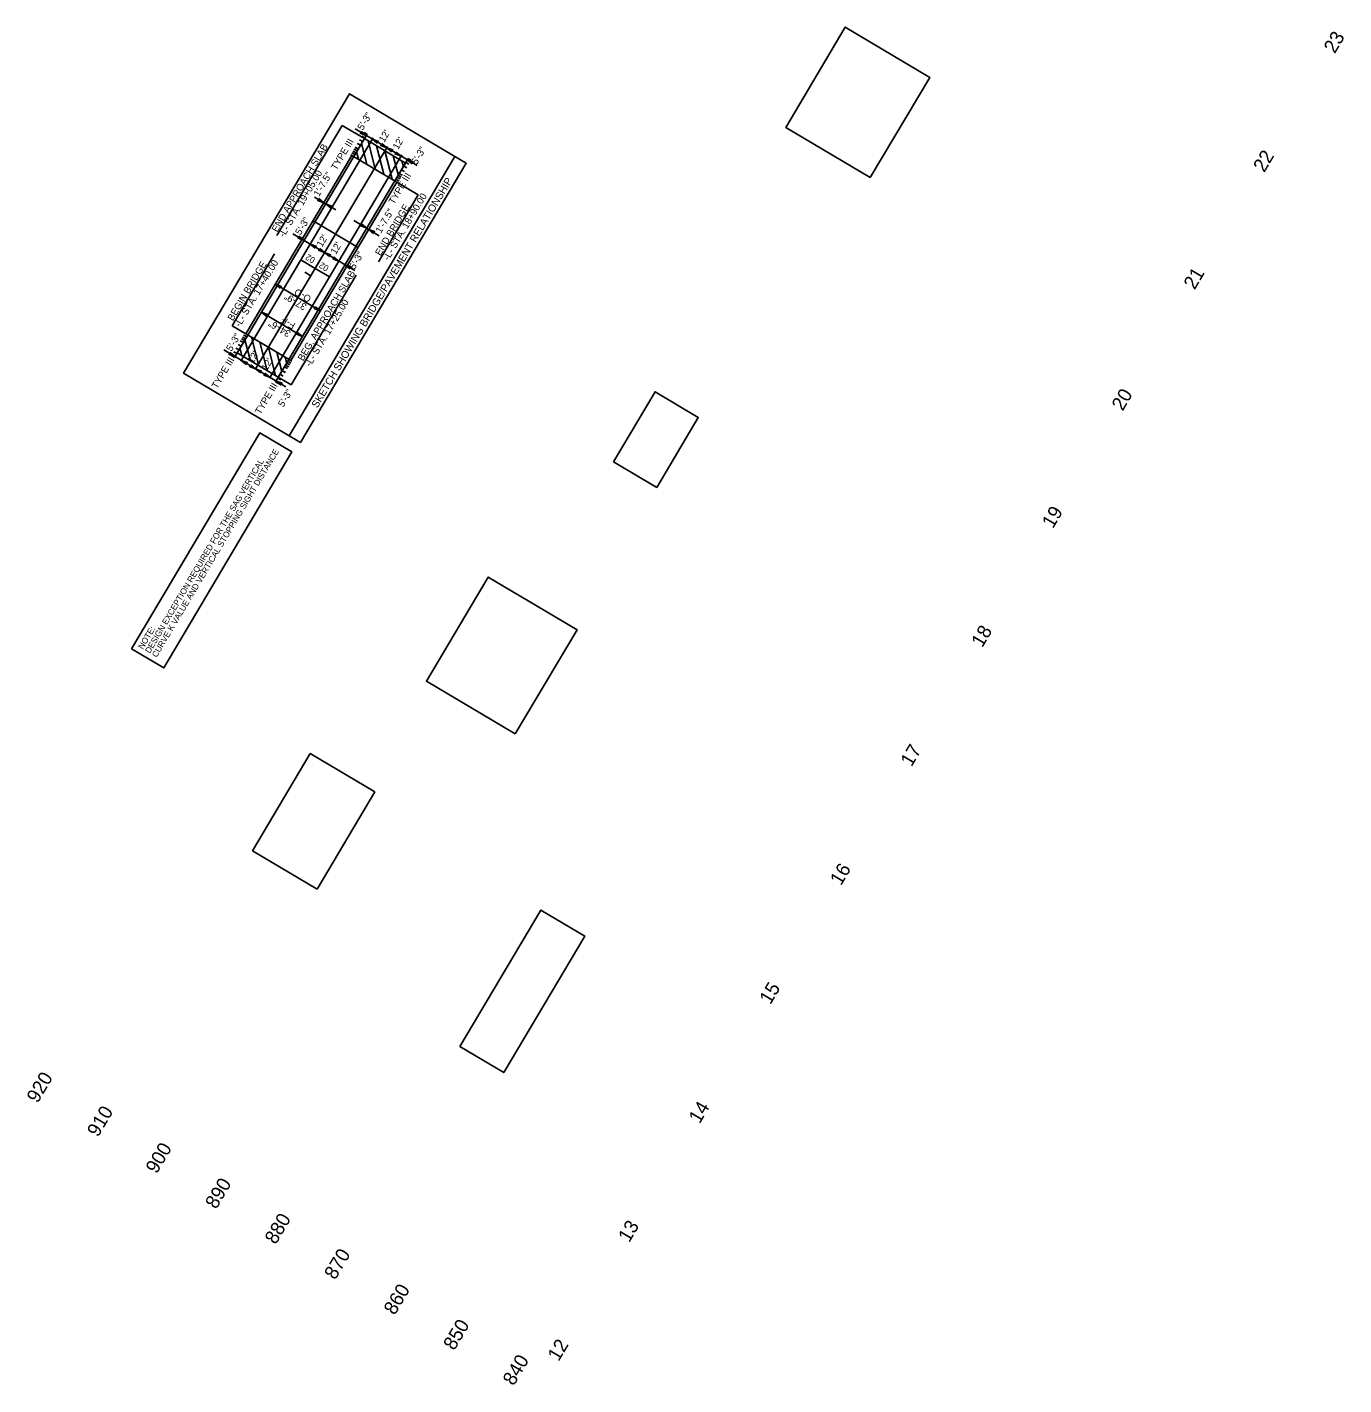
# Model space of a CAD drawing. Extents: x 2138768 to 2143723, y 406633 to 414335.
# Drawn here: x 2142621 to 2143572, y 412821 to 413802 of the extents above; entities that cross this region are included whole.
import ezdxf

# ---------------------------------------------------------------- set-up
doc = ezdxf.new("R2010")
doc.units = 0
for name, color, linetype in [('Exist Vertical Profile Horizontal Axis Label Major', 7, 'Continuous'), ('Exist Vertical Profile Vertical Axis Label', 7, 'Continuous'), ('Old_Level_1', 7, 'Continuous'), ('Prop Approach Slab', 7, 'Continuous'), ('Prop Approach Slab Hatching', 7, 'Continuous'), ('Prop Dimension', 7, 'Continuous'), ('Prop Dimension Text', 7, 'Continuous'), ('Prop EOT', 7, 'Continuous'), ('Prop Grid Mask', 7, 'Continuous'), ('Prop Horizontal Alignment', 7, 'Continuous'), ('Prop Horizontal Alignment Tick Small', 7, 'Continuous'), ('Prop Roadway Bridge', 7, 'Continuous'), ('Prop Structure Anchor Unit CELL', 7, 'Continuous'), ('Prop Superelevation  Arrow CELL', 7, 'Continuous'), ('Prop Terminator CELL', 7, 'Continuous')]:
    doc.layers.add(name, color=color, linetype=linetype)

msp = doc.modelspace()

# ---------------------------------------------------------------- linework, layer by layer
at = {"layer": 'Prop Approach Slab'}
for p, q in [((2142857.09, 413708.21), (2142864.74, 413721.11)), ((2142894.41, 413703.5), (2142864.74, 413721.11)), ((2142886.76, 413690.6), (2142894.41, 413703.5)), ((2142780.53, 413579.22), (2142772.87, 413566.32)), ((2142802.54, 413548.71), (2142772.87, 413566.32)), ((2142810.2, 413561.61), (2142802.54, 413548.71))]:
    msp.add_line(p, q, dxfattribs=at)
at = {"layer": 'Prop Approach Slab Hatching'}
for p, q in [((2142860.5, 413706.19), (2142859.11, 413711.62)), ((2142866.58, 413702.58), (2142862.72, 413717.7)), ((2142872.66, 413698.97), (2142867.42, 413719.52)), ((2142878.74, 413695.36), (2142873.5, 413715.91)), ((2142884.82, 413691.75), (2142879.58, 413712.31)), ((2142889.13, 413695.09), (2142885.66, 413708.7)), ((2142892.74, 413701.17), (2142891.74, 413705.09)), ((2142782.36, 413560.69), (2142778.5, 413575.81)), ((2142788.44, 413557.08), (2142783.2, 413577.63)), ((2142776.28, 413564.3), (2142774.98, 413569.39)), ((2142794.52, 413553.47), (2142789.28, 413574.03)), ((2142800.6, 413549.86), (2142795.36, 413570.42)), ((2142805, 413552.86), (2142801.44, 413566.81)), ((2142808.61, 413558.94), (2142807.52, 413563.2))]:
    msp.add_line(p, q, dxfattribs=at)
at = {"layer": 'Prop Dimension'}
for p, q in [((2142858.01, 413728.18), (2142902.79, 413701.6)), ((2142828.71, 413678.81), (2142844.12, 413669.67)), ((2142857.04, 413662), (2142875.55, 413651.02)), ((2142813.06, 413652.45), (2142857.84, 413625.87)), ((2142800.45, 413615.98), (2142832.92, 413596.71)), ((2142790.35, 413595.78), (2142820.02, 413578.17)), ((2142763.19, 413568.43), (2142807.98, 413541.85))]:
    msp.add_line(p, q, dxfattribs=at)
at = {"layer": 'Prop Dimension Text'}
for p, q in [((2142801.48, 413651.19), (2142848.65, 413730.66)), ((2142864.74, 413721.11), (2142848.65, 413730.66)), ((2142888.15, 413689.77), (2142903.62, 413680.59)), ((2142874.85, 413632.13), (2142903.62, 413680.59)), ((2142799.92, 413637.78), (2142769.17, 413585.96)), ((2142811.79, 413543.22), (2142858.85, 413622.5)), ((2142779.13, 413580.05), (2142769.17, 413585.96)), ((2142802.54, 413548.71), (2142811.79, 413543.22))]:
    msp.add_line(p, q, dxfattribs=at)
for points in [[(2142930.14, 413708.26), (2142810.34, 413506.43), (2142734.14, 413551.65), (2142853.94, 413753.49)], [(2142810.34, 413506.43), (2142930.14, 413708.26), (2142938.37, 413703.37), (2142818.58, 413501.54)], [(2142696.58, 413352.6), (2142789.13, 413508.54), (2142812.38, 413494.75), (2142719.82, 413338.8)]]:
    msp.add_lwpolyline(points, close=True, dxfattribs=at)
at = {"layer": 'Prop EOT'}
for p, q in [((2142775.47, 413560.42), (2142871.17, 413721.66)), ((2142796.11, 413548.17), (2142891.81, 413709.41))]:
    msp.add_line(p, q, dxfattribs=at)
at = {"layer": 'Prop Grid Mask'}
for points in [[(2143230.28, 413692.99), (2143273.26, 413765.4), (2143212.19, 413801.65), (2143169.21, 413729.24)], [(2143044.7, 413487.72), (2143074.73, 413538.32), (2143106.03, 413519.74), (2143076, 413469.14)], [(2142973.78, 413291.05), (2143018.47, 413366.34), (2142954.28, 413404.43), (2142909.6, 413329.15)], [(2142830.66, 413178.99), (2142872.3, 413249.15), (2142825.6, 413276.87), (2142783.96, 413206.71)], [(2142933.73, 413065.29), (2142992.24, 413163.86), (2143023.92, 413145.05), (2142965.42, 413046.48)]]:
    msp.add_lwpolyline(points, close=True, dxfattribs=at)
at = {"layer": 'Prop Horizontal Alignment'}
msp.add_line((2142785.79, 413554.29), (2142881.49, 413715.53), dxfattribs=at)
at = {"layer": 'Prop Horizontal Alignment Tick Small'}
msp.add_line((2142825.99, 413622.01), (2142821.69, 413624.56), dxfattribs=at)
at = {"layer": 'Prop Roadway Bridge'}
for p, q in [((2142779.13, 413580.05), (2142855.69, 413709.04)), ((2142780.53, 413579.22), (2142857.09, 413708.21)), ((2142888.15, 413689.77), (2142855.69, 413709.04)), ((2142810.2, 413561.61), (2142886.76, 413690.6)), ((2142811.59, 413560.78), (2142888.15, 413689.77)), ((2142859.87, 413642.6), (2142827.83, 413661.62)), ((2142811.59, 413560.78), (2142779.13, 413580.05))]:
    msp.add_line(p, q, dxfattribs=at)
at = {"layer": 'Prop Structure Anchor Unit CELL'}
for p, q in [((2142857.09, 413708.21), (2142866.66, 413724.33)), ((2142863.05, 413722.18), (2142863.64, 413723.16)), ((2142865.06, 413721.65), (2142863.34, 413722.67)), ((2142864.65, 413724.86), (2142865.23, 413725.85)), ((2142866.66, 413724.33), (2142864.94, 413725.36)), ((2142856.67, 413711.43), (2142857.26, 413712.41)), ((2142858.68, 413710.9), (2142856.96, 413711.92)), ((2142857.47, 413712.77), (2142858.05, 413713.76)), ((2142859.48, 413712.24), (2142857.76, 413713.26)), ((2142858.27, 413714.11), (2142858.85, 413715.1)), ((2142860.28, 413713.59), (2142858.56, 413714.61)), ((2142859.86, 413716.8), (2142860.45, 413717.79)), ((2142861.87, 413716.27), (2142860.15, 413717.29)), ((2142861.46, 413719.49), (2142862.04, 413720.47)), ((2142863.47, 413718.96), (2142861.75, 413719.98)), ((2142855.08, 413708.74), (2142855.66, 413709.72)), ((2142857.09, 413708.21), (2142855.37, 413709.23)), ((2142855.87, 413710.08), (2142856.46, 413711.07)), ((2142857.89, 413709.55), (2142856.17, 413710.58)), ((2142886.76, 413690.6), (2142896.33, 413706.73)), ((2142894.73, 413704.04), (2142896.45, 413703.02)), ((2142896.16, 413702.53), (2142896.74, 413703.51)), ((2142896.33, 413706.73), (2142898.05, 413705.71)), ((2142897.75, 413705.21), (2142898.34, 413706.2)), ((2142887.55, 413691.95), (2142889.27, 413690.93)), ((2142888.35, 413693.29), (2142890.07, 413692.27)), ((2142889.15, 413694.63), (2142890.87, 413693.61)), ((2142889.78, 413691.78), (2142890.36, 413692.76)), ((2142889.95, 413695.98), (2142891.67, 413694.96)), ((2142890.58, 413693.12), (2142891.16, 413694.1)), ((2142891.37, 413694.46), (2142891.96, 413695.45)), ((2142891.54, 413698.66), (2142893.26, 413697.64)), ((2142892.97, 413697.15), (2142893.55, 413698.14)), ((2142893.14, 413701.35), (2142894.86, 413700.33)), ((2142894.56, 413699.84), (2142895.15, 413700.82)), ((2142886.76, 413690.6), (2142888.48, 413689.58)), ((2142888.18, 413689.09), (2142888.77, 413690.07)), ((2142888.98, 413690.43), (2142889.57, 413691.42)), ((2142780.53, 413579.22), (2142770.96, 413563.1)), ((2142775.91, 413575.36), (2142775.33, 413574.37)), ((2142777.34, 413573.85), (2142775.62, 413574.87)), ((2142776.71, 413576.7), (2142776.12, 413575.72)), ((2142778.14, 413575.19), (2142776.42, 413576.21)), ((2142777.5, 413578.05), (2142776.92, 413577.06)), ((2142778.93, 413576.53), (2142777.21, 413577.55)), ((2142778.3, 413579.39), (2142777.72, 413578.41)), ((2142779.73, 413577.88), (2142778.01, 413578.9)), ((2142779.1, 413580.73), (2142778.52, 413579.75)), ((2142780.53, 413579.22), (2142778.81, 413580.24)), ((2142769.53, 413564.61), (2142768.95, 413563.63)), ((2142771.12, 413567.3), (2142770.54, 413566.31)), ((2142772.55, 413565.78), (2142770.83, 413566.81)), ((2142772.72, 413569.99), (2142772.14, 413569)), ((2142774.15, 413568.47), (2142772.43, 413569.49)), ((2142774.31, 413572.67), (2142773.73, 413571.69)), ((2142775.74, 413571.16), (2142774.02, 413572.18)), ((2142770.96, 413563.1), (2142769.24, 413564.12)), ((2142810.2, 413561.61), (2142800.63, 413545.49)), ((2142807.01, 413556.24), (2142808.73, 413555.22)), ((2142807.8, 413557.58), (2142809.52, 413556.56)), ((2142809.02, 413555.71), (2142808.43, 413554.72)), ((2142808.6, 413558.92), (2142810.32, 413557.9)), ((2142809.81, 413557.05), (2142809.23, 413556.07)), ((2142809.4, 413560.27), (2142811.12, 413559.25)), ((2142810.61, 413558.4), (2142810.03, 413557.41)), ((2142810.2, 413561.61), (2142811.92, 413560.59)), ((2142811.41, 413559.74), (2142810.83, 413558.76)), ((2142812.21, 413561.08), (2142811.62, 413560.1)), ((2142800.63, 413545.49), (2142802.35, 413544.47)), ((2142802.64, 413544.96), (2142802.05, 413543.97)), ((2142802.22, 413548.18), (2142803.94, 413547.15)), ((2142804.23, 413547.65), (2142803.65, 413546.66)), ((2142803.82, 413550.86), (2142805.54, 413549.84)), ((2142805.83, 413550.33), (2142805.24, 413549.35)), ((2142805.41, 413553.55), (2142807.13, 413552.53)), ((2142807.42, 413553.02), (2142806.84, 413552.04))]:
    msp.add_line(p, q, dxfattribs=at)
at = {"layer": 'Prop Superelevation  Arrow CELL'}
for q in [(2142818.83, 413633.47), (2142839.47, 413621.22)]:
    msp.add_line((2142829.15, 413627.35), q, dxfattribs=at)
at = {"layer": 'Prop Terminator CELL'}
for points in [[(2142862.62, 413726.35), (2142866.09, 413723.38), (2142861.79, 413725), (2142862.7, 413725.4)], [(2142874.08, 413717.74), (2142870.61, 413720.7), (2142874.91, 413719.08), (2142874, 413718.69)], [(2142877.45, 413717.54), (2142880.93, 413714.58), (2142876.63, 413716.2), (2142877.53, 413716.59)], [(2142884.4, 413711.62), (2142880.93, 413714.58), (2142885.23, 413712.96), (2142884.32, 413712.56)], [(2142887.77, 413711.42), (2142891.25, 413708.45), (2142886.95, 413710.08), (2142887.85, 413710.47)], [(2142899.24, 413702.81), (2142895.76, 413705.77), (2142900.06, 413704.15), (2142899.16, 413703.76)], [(2142831.92, 413677.81), (2142835.4, 413674.85), (2142831.1, 413676.47), (2142832, 413676.86)], [(2142840.27, 413671.05), (2142836.79, 413674.02), (2142841.09, 413672.4), (2142840.19, 413672)], [(2142862.99, 413659.37), (2142866.46, 413656.41), (2142862.16, 413658.03), (2142863.06, 413658.43)], [(2142871.33, 413652.62), (2142867.86, 413655.58), (2142872.16, 413653.96), (2142871.25, 413653.56)], [(2142817.67, 413650.61), (2142821.14, 413647.65), (2142816.84, 413649.27), (2142817.75, 413649.67)], [(2142829.13, 413642.01), (2142825.66, 413644.97), (2142829.96, 413643.35), (2142829.05, 413642.95)], [(2142832.5, 413641.81), (2142835.98, 413638.84), (2142831.68, 413640.47), (2142832.58, 413640.86)], [(2142839.45, 413635.88), (2142835.98, 413638.84), (2142840.28, 413637.22), (2142839.37, 413636.83)], [(2142842.82, 413635.68), (2142846.3, 413632.72), (2142842, 413634.34), (2142842.9, 413634.74)], [(2142854.28, 413627.08), (2142850.81, 413630.04), (2142855.11, 413628.42), (2142854.21, 413628.02)], [(2142803.93, 413613.01), (2142800.45, 413615.98), (2142804.75, 413614.35), (2142803.85, 413613.96)], [(2142793.83, 413592.81), (2142790.35, 413595.78), (2142794.65, 413594.15), (2142793.75, 413593.76)], [(2142829.44, 413599.67), (2142832.92, 413596.71), (2142828.62, 413598.33), (2142829.52, 413598.72)], [(2142816.55, 413581.13), (2142820.02, 413578.17), (2142815.72, 413579.79), (2142816.62, 413580.18)], [(2142767.8, 413566.6), (2142771.28, 413563.63), (2142766.98, 413565.26), (2142767.88, 413565.65)], [(2142779.26, 413557.99), (2142775.79, 413560.95), (2142780.09, 413559.33), (2142779.19, 413558.94)], [(2142782.64, 413557.79), (2142786.11, 413554.83), (2142781.81, 413556.45), (2142782.71, 413556.85)], [(2142789.58, 413551.87), (2142786.11, 413554.83), (2142790.41, 413553.21), (2142789.51, 413552.81)], [(2142792.95, 413551.67), (2142796.43, 413548.7), (2142792.13, 413550.33), (2142793.03, 413550.72)], [(2142804.42, 413543.06), (2142800.94, 413546.02), (2142805.24, 413544.4), (2142804.34, 413544.01)]]:
    msp.add_lwpolyline(points, close=True, dxfattribs=at)

# ---------------------------------------------------------------- texts
at = {"layer": 'Exist Vertical Profile Horizontal Axis Label Major'}
for s, p in [('23', (2143565.82, 413782.01)), ('22', (2143514.87, 413696.15)), ('21', (2143464.57, 413611.41)), ('20', (2143412.59, 413523.83)), ('19', (2143362.22, 413438.98)), ('18', (2143311.16, 413352.95)), ('17', (2143260.05, 413266.84)), ('16', (2143209.09, 413180.97)), ('15', (2143158.08, 413095.03)), ('14', (2143106.99, 413008.96)), ('13', (2143056.03, 412923.1)), ('12', (2143005.07, 412837.25))]:
    msp.add_text(s, height=10, rotation=59.30926, dxfattribs=at).set_placement(p)
at = {"layer": 'Exist Vertical Profile Vertical Axis Label'}
for s, p in [('920', (2142628.69, 413023.81)), ('910', (2142672.3, 412999.32)), ('900', (2142714.68, 412972.77)), ('890', (2142757.68, 412947.25)), ('880', (2142800.68, 412921.73)), ('870', (2142843.67, 412896.21)), ('860', (2142886.67, 412870.69)), ('850', (2142929.67, 412845.17)), ('840', (2142972.66, 412819.65))]:
    msp.add_text(s, height=10, rotation=59.30926, dxfattribs=at).set_placement(p)
at = {"layer": 'Old_Level_1'}
for s, p in [('CURVE K VALUE AND VERTICAL STOPPING SIGHT DISTANCE', (2142714.68, 413345.96)), ('DESIGN EXCEPTION REQUIRED FOR THE SAG VERTICAL', (2142709.75, 413348.88)), ('NOTE:', (2142704.81, 413351.81))]:
    msp.add_text(s, height=4.375, rotation=59.30926, dxfattribs=at).set_placement(p)
at = {"layer": 'Prop Dimension Text'}
for s, height, rotation, p in [('5\'-3"', 5, 59.30926, (2142863.61, 413726.74)), ("12'", 5, 59.30926, (2142879.08, 413718.02)), ("12'", 5, 59.30926, (2142889.12, 413712.83)), ('END APPROACH SLAB', 5, 59.30926, (2142801.7, 413653.14)), ('TYPE III', 5, 59.30926, (2142844.58, 413697.85)), ('5\'-3"', 5, 59.30926, (2142902.67, 413701.93)), ('-L- STA. 19+05.00', 5, 59.30926, (2142806.64, 413649.33)), ('SKETCH SHOWING BRIDGE/PAVEMENT RELATIONSHIP', 5.36, 59.30926, (2142830.81, 413526.15)), ('1\'-7.5"', 5, 59.30926, (2142831.97, 413678.83)), ('TYPE III', 5, 59.30926, (2142886.16, 413673.17)), ('END BRIDGE', 5, 59.30926, (2142876.39, 413636.1)), ('-L- STA. 18+90.00', 5, 59.30926, (2142882.17, 413632.65)), ('5\'-3"', 5, 59.30926, (2142818.66, 413651.01)), ('1\'-7.5"', 5, 59.30926, (2142876.66, 413652.31)), ("12'", 5, 59.30926, (2142834.13, 413642.29)), ("12'", 5, 59.30926, (2142844.17, 413637.09)), ('-L- STA. 17+40.00', 5, 59.30926, (2142774.86, 413584.56)), ('5\'-3"', 5, 59.30926, (2142857.72, 413626.2)), ('BEGIN BRIDGE', 5, 59.30926, (2142769.8, 413589.02)), ('BEG. APPROACH SLAB', 5, 59.30926, (2142820.49, 413560.07)), ('37\'-9"', 5, 149.30926, (2142823.53, 413601.07)), ('O-O', 5, 149.30926, (2142826.88, 413606.71)), ('-L- STA. 17+25.00', 5, 59.30926, (2142825.76, 413555.99)), ('34\'-6"', 5, 149.30926, (2142812.03, 413581.7)), ('F-F', 5, 149.30926, (2142815.38, 413587.34)), ('5\'-3"', 5, 59.30926, (2142768.79, 413567)), ("12'", 5, 59.30926, (2142784.26, 413558.27)), ('TYPE III', 5, 59.30926, (2142758.35, 413539.98)), ("12'", 5, 59.30926, (2142794.31, 413553.08)), ('TYPE III', 5, 59.30926, (2142789.61, 413521.43)), ('5\'-3"', 5, 59.30926, (2142806.28, 413526.83))]:
    msp.add_text(s, height=height, rotation=rotation, dxfattribs=at).set_placement(p)
at = {"layer": 'Prop Superelevation  Arrow CELL'}
for p in [(2142829.66, 413634.59), (2142839.5, 413628.75)]:
    msp.add_text('02', height=4.5, rotation=149.30926, dxfattribs=at).set_placement(p)

doc.saveas('drawing.dxf')
